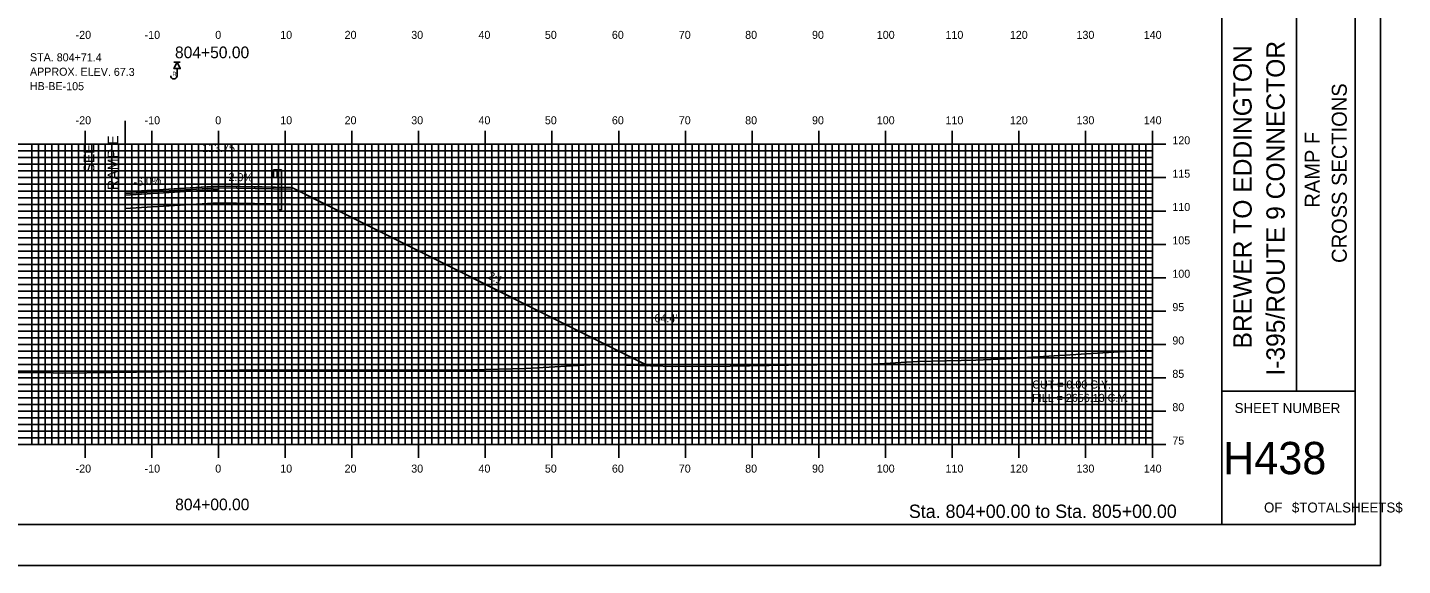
# Model space of a CAD drawing. Extents: x 485 to 829, y -1658 to -1438.
# Drawn here: x 622.5 to 828.6, y -1657.7 to -1577.1 of the extents above; entities that cross this region are included whole.
import ezdxf

# ---------------------------------------------------------------- set-up
doc = ezdxf.new("R2010")
doc.units = 0
for name, color, linetype in [('ANNOTATION', 7, 'Continuous'), ('BORDER', 7, 'Continuous'), ('BORING - REFUSAL', 7, 'Continuous'), ('D_Guardrail_Beam_Lt', 7, 'Continuous'), ('D_Roadway_Centerline', 7, 'Continuous'), ('D_Roadway_Centerline_Text', 7, 'Continuous'), ('D_Roadway_Edge_Shoulder', 7, 'Continuous'), ('D_Roadway_Edge_TW', 7, 'Continuous'), ('D_Roadway_Pavement', 7, 'Continuous'), ('D_Roadway_SlopeLines', 7, 'Continuous'), ('D_Roadway_SubGrade', 7, 'Continuous'), ('D_Text_Standard', 7, 'Continuous'), ('Default', 7, 'Continuous'), ('H_V ANNOTATION', 7, 'Continuous'), ('MAJOR', 7, 'Continuous'), ('MINOR', 7, 'Continuous'), ('PLOT BOUNDARY', 7, 'Continuous'), ('S_Roadway_Centerline', 7, 'Continuous')]:
    doc.layers.add(name, color=color, linetype=linetype)

msp = doc.modelspace()

# ---------------------------------------------------------------- linework, layer by layer
at = {"layer": 'BORDER'}
for p, q in [((801.53, -1651.6), (801.53, -1441.6)), ((812.72, -1631.6), (812.72, -1561.6)), ((801.53, -1631.6), (821.53, -1631.6))]:
    msp.add_line(p, q, dxfattribs=at)
msp.add_lwpolyline([(501.53, -1651.6), (821.53, -1651.6), (821.53, -1441.6), (501.53, -1441.6)], close=True, dxfattribs=at)
at = {"layer": 'BORING - REFUSAL'}
for p, q in [((645.41, -1582.3), (644.45, -1582.3)), ((644.93, -1583.26), (644.93, -1584.32))]:
    msp.add_line(p, q, dxfattribs=at)
msp.add_lwpolyline([(644.93, -1582.3), (645.41, -1583.26), (644.45, -1583.26)], close=True, dxfattribs=at)
msp.add_arc((644.45, -1584.32), 0.485, 180, 0, dxfattribs=at)
at = {"layer": 'D_Guardrail_Beam_Lt'}
for p, q in [((659.31, -1598.54), (659.17, -1598.64)), ((659.17, -1598.78), (659.37, -1598.92)), ((659.37, -1599.12), (659.17, -1599.25)), ((659.17, -1599.4), (659.31, -1599.5)), ((659.4, -1598.52), (659.33, -1598.53)), ((659.33, -1599.5), (659.4, -1599.52)), ((659.4, -1598.44), (660.09, -1598.44)), ((659.4, -1599.6), (659.4, -1598.44)), ((659.4, -1598.98), (659.4, -1599.05)), ((659.93, -1598.44), (659.93, -1599.6)), ((660.03, -1598.44), (660.03, -1599.6)), ((660.09, -1598.44), (660.56, -1598.44)), ((660.09, -1598.44), (660.09, -1599.6)), ((660.56, -1598.44), (660.56, -1604.44)), ((660.09, -1599.6), (659.4, -1599.6)), ((660.07, -1604.44), (660.07, -1599.6)), ((660.07, -1604.44), (660.56, -1604.44))]:
    msp.add_line(p, q, dxfattribs=at)
for centre, major_axis, start_param, end_param in [((659.22, -1598.71), (-0.0877, 0), 5.323254, 7.243116), ((659.22, -1599.33), (-0.0877, 0), 5.323254, 7.243116), ((659.34, -1598.57), (-0.0417, 0), 4.907132, 5.323254), ((659.34, -1599.46), (-0.0417, 0), 0.959931, 1.376053), ((659.32, -1598.98), (0.0789, 0), 0, 0.959931), ((659.32, -1599.05), (0.0789, 0), 5.323254, 6.283185)]:
    msp.add_ellipse(centre, major_axis=major_axis, ratio=0.995501, start_param=start_param, end_param=end_param, dxfattribs=at)
at = {"layer": 'D_Roadway_Centerline'}
msp.add_lwpolyline([(637.13, -1601.7), (648.53, -1601.02), (651.13, -1600.86), (657.67, -1600.99), (659.13, -1601.02), (659.67, -1601.03), (662.13, -1601.08), (666.39, -1603.21), (667.34, -1603.68), (675.21, -1607.61), (715.57, -1627.8)], dxfattribs=at)
at = {"layer": 'D_Roadway_Edge_Shoulder'}
for points in [[(651.13, -1600.86), (659.13, -1601.02), (659.13, -1601.02), (662.13, -1601.08), (662.13, -1601.33), (651.13, -1601.11)], [(651.13, -1600.86), (662.13, -1601.08), (662.13, -1601.33), (651.13, -1601.11)]]:
    msp.add_lwpolyline(points, close=True, dxfattribs=at)
at = {"layer": 'D_Roadway_Edge_TW'}
msp.add_lwpolyline([(637.13, -1601.7), (651.13, -1600.86), (651.13, -1601.11), (637.13, -1601.95)], close=True, dxfattribs=at)
at = {"layer": 'D_Roadway_Pavement'}
msp.add_lwpolyline([(637.13, -1601.95), (651.13, -1601.11), (651.13, -1601.36), (637.13, -1602.2)], close=True, dxfattribs=at)
msp.add_lwpolyline([(651.13, -1601.11), (651.13, -1601.36)], dxfattribs=at)
msp.add_lwpolyline([(651.13, -1601.11), (651.13, -1601.36)], dxfattribs=at)
msp.add_lwpolyline([(651.13, -1601.11), (651.13, -1601.36)], dxfattribs=at)
at = {"layer": 'D_Roadway_SlopeLines'}
msp.add_lwpolyline([(662.13, -1601.08), (715.57, -1627.8)], dxfattribs=at)
msp.add_lwpolyline([(662.13, -1601.08), (715.57, -1627.8)], dxfattribs=at)
at = {"layer": 'D_Roadway_SubGrade'}
msp.add_line((637.13, -1591.06), (637.13, -1604.2), dxfattribs=at)
for points in [[(637.13, -1602.2), (651.13, -1601.36), (651.13, -1603.36), (637.13, -1604.2)], [(651.13, -1601.36), (651.13, -1601.11), (662.13, -1601.33), (662.13, -1601.08), (667.34, -1603.68), (651.13, -1603.36)]]:
    msp.add_lwpolyline(points, close=True, dxfattribs=at)
at = {"layer": 'Default'}
msp.add_line((637.13, -1604.2), (637.13, -1593.39), dxfattribs=at)
at = {"layer": 'MAJOR'}
for p, q in [((631.13, -1592.6), (631.13, -1594.6)), ((641.13, -1592.6), (641.13, -1594.6)), ((651.13, -1592.6), (651.13, -1594.6)), ((661.13, -1592.6), (661.13, -1594.6)), ((671.13, -1592.6), (671.13, -1594.6)), ((681.13, -1592.6), (681.13, -1594.6)), ((691.13, -1592.6), (691.13, -1594.6)), ((701.13, -1592.6), (701.13, -1594.6)), ((711.13, -1592.6), (711.13, -1594.6)), ((721.13, -1592.6), (721.13, -1594.6)), ((731.13, -1592.6), (731.13, -1594.6)), ((741.13, -1592.6), (741.13, -1594.6)), ((751.13, -1592.6), (751.13, -1594.6)), ((761.13, -1592.6), (761.13, -1594.6)), ((771.13, -1592.6), (771.13, -1594.6)), ((781.13, -1592.6), (781.13, -1594.6)), ((791.13, -1592.6), (791.13, -1594.6)), ((511.13, -1594.6), (791.13, -1594.6)), ((511.13, -1594.6), (791.13, -1594.6)), ((631.13, -1639.6), (631.13, -1594.6)), ((641.13, -1639.6), (641.13, -1594.6)), ((651.13, -1639.6), (651.13, -1594.6)), ((661.13, -1639.6), (661.13, -1594.6)), ((671.13, -1639.6), (671.13, -1594.6)), ((681.13, -1639.6), (681.13, -1594.6)), ((691.13, -1639.6), (691.13, -1594.6)), ((701.13, -1639.6), (701.13, -1594.6)), ((711.13, -1639.6), (711.13, -1594.6)), ((721.13, -1639.6), (721.13, -1594.6)), ((731.13, -1639.6), (731.13, -1594.6)), ((741.13, -1639.6), (741.13, -1594.6)), ((751.13, -1639.6), (751.13, -1594.6)), ((761.13, -1639.6), (761.13, -1594.6)), ((771.13, -1639.6), (771.13, -1594.6)), ((781.13, -1639.6), (781.13, -1594.6)), ((793.14, -1594.6), (789.13, -1594.6)), ((791.13, -1639.6), (791.13, -1594.6)), ((791.13, -1639.6), (791.13, -1594.6)), ((511.13, -1599.6), (791.13, -1599.6)), ((793.14, -1599.6), (789.13, -1599.6)), ((511.13, -1604.6), (791.13, -1604.6)), ((793.14, -1604.6), (789.13, -1604.6)), ((511.13, -1609.6), (791.13, -1609.6)), ((793.14, -1609.6), (789.13, -1609.6)), ((511.13, -1614.6), (791.13, -1614.6)), ((793.14, -1614.6), (789.13, -1614.6)), ((511.13, -1619.6), (791.13, -1619.6)), ((793.14, -1619.6), (789.13, -1619.6)), ((511.13, -1624.6), (791.13, -1624.6)), ((793.14, -1624.6), (789.13, -1624.6)), ((511.13, -1629.6), (791.13, -1629.6)), ((793.14, -1629.6), (789.13, -1629.6)), ((511.13, -1634.6), (791.13, -1634.6)), ((793.14, -1634.6), (789.13, -1634.6)), ((511.13, -1639.6), (791.13, -1639.6)), ((511.13, -1639.6), (791.13, -1639.6)), ((631.13, -1641.61), (631.13, -1639.6)), ((641.13, -1641.61), (641.13, -1639.6)), ((651.13, -1641.61), (651.13, -1639.6)), ((661.13, -1641.61), (661.13, -1639.6)), ((671.13, -1641.61), (671.13, -1639.6)), ((681.13, -1641.61), (681.13, -1639.6)), ((691.13, -1641.61), (691.13, -1639.6)), ((701.13, -1641.61), (701.13, -1639.6)), ((711.13, -1641.61), (711.13, -1639.6)), ((721.13, -1641.61), (721.13, -1639.6)), ((731.13, -1641.61), (731.13, -1639.6)), ((741.13, -1641.61), (741.13, -1639.6)), ((751.13, -1641.61), (751.13, -1639.6)), ((761.13, -1641.61), (761.13, -1639.6)), ((771.13, -1641.61), (771.13, -1639.6)), ((781.13, -1641.61), (781.13, -1639.6)), ((793.14, -1639.6), (789.13, -1639.6)), ((791.13, -1641.61), (791.13, -1639.6))]:
    msp.add_line(p, q, dxfattribs=at)
at = {"layer": 'MINOR'}
for p, q in [((623.13, -1639.6), (623.13, -1594.6)), ((624.13, -1639.6), (624.13, -1594.6)), ((625.13, -1639.6), (625.13, -1594.6)), ((626.13, -1639.6), (626.13, -1594.6)), ((627.13, -1639.6), (627.13, -1594.6)), ((628.13, -1639.6), (628.13, -1594.6)), ((629.13, -1639.6), (629.13, -1594.6)), ((630.13, -1639.6), (630.13, -1594.6)), ((632.13, -1639.6), (632.13, -1594.6)), ((633.13, -1639.6), (633.13, -1594.6)), ((634.13, -1639.6), (634.13, -1594.6)), ((635.13, -1639.6), (635.13, -1594.6)), ((636.13, -1639.6), (636.13, -1594.6)), ((637.13, -1639.6), (637.13, -1594.6)), ((638.13, -1639.6), (638.13, -1594.6)), ((639.13, -1639.6), (639.13, -1594.6)), ((640.13, -1639.6), (640.13, -1594.6)), ((642.13, -1639.6), (642.13, -1594.6)), ((643.13, -1639.6), (643.13, -1594.6)), ((644.13, -1639.6), (644.13, -1594.6)), ((645.13, -1639.6), (645.13, -1594.6)), ((646.13, -1639.6), (646.13, -1594.6)), ((647.13, -1639.6), (647.13, -1594.6)), ((648.13, -1639.6), (648.13, -1594.6)), ((649.13, -1639.6), (649.13, -1594.6)), ((650.13, -1639.6), (650.13, -1594.6)), ((652.13, -1639.6), (652.13, -1594.6)), ((653.13, -1639.6), (653.13, -1594.6)), ((654.13, -1639.6), (654.13, -1594.6)), ((655.13, -1639.6), (655.13, -1594.6)), ((656.13, -1639.6), (656.13, -1594.6)), ((657.13, -1639.6), (657.13, -1594.6)), ((658.13, -1639.6), (658.13, -1594.6)), ((659.13, -1639.6), (659.13, -1594.6)), ((660.13, -1639.6), (660.13, -1594.6)), ((662.13, -1639.6), (662.13, -1594.6)), ((663.13, -1639.6), (663.13, -1594.6)), ((664.13, -1639.6), (664.13, -1594.6)), ((665.13, -1639.6), (665.13, -1594.6)), ((666.13, -1639.6), (666.13, -1594.6)), ((667.13, -1639.6), (667.13, -1594.6)), ((668.13, -1639.6), (668.13, -1594.6)), ((669.13, -1639.6), (669.13, -1594.6)), ((670.13, -1639.6), (670.13, -1594.6)), ((672.13, -1639.6), (672.13, -1594.6)), ((673.13, -1639.6), (673.13, -1594.6)), ((674.13, -1639.6), (674.13, -1594.6)), ((675.13, -1639.6), (675.13, -1594.6)), ((676.13, -1639.6), (676.13, -1594.6)), ((677.13, -1639.6), (677.13, -1594.6)), ((678.13, -1639.6), (678.13, -1594.6)), ((679.13, -1639.6), (679.13, -1594.6)), ((680.13, -1639.6), (680.13, -1594.6)), ((682.13, -1639.6), (682.13, -1594.6)), ((683.13, -1639.6), (683.13, -1594.6)), ((684.13, -1639.6), (684.13, -1594.6)), ((685.13, -1639.6), (685.13, -1594.6)), ((686.13, -1639.6), (686.13, -1594.6)), ((687.13, -1639.6), (687.13, -1594.6)), ((688.13, -1639.6), (688.13, -1594.6)), ((689.13, -1639.6), (689.13, -1594.6)), ((690.13, -1639.6), (690.13, -1594.6)), ((692.13, -1639.6), (692.13, -1594.6)), ((693.13, -1639.6), (693.13, -1594.6)), ((694.13, -1639.6), (694.13, -1594.6)), ((695.13, -1639.6), (695.13, -1594.6)), ((696.13, -1639.6), (696.13, -1594.6)), ((697.13, -1639.6), (697.13, -1594.6)), ((698.13, -1639.6), (698.13, -1594.6)), ((699.13, -1639.6), (699.13, -1594.6)), ((700.13, -1639.6), (700.13, -1594.6)), ((702.13, -1639.6), (702.13, -1594.6)), ((703.13, -1639.6), (703.13, -1594.6)), ((704.13, -1639.6), (704.13, -1594.6)), ((705.13, -1639.6), (705.13, -1594.6)), ((706.13, -1639.6), (706.13, -1594.6)), ((707.13, -1639.6), (707.13, -1594.6)), ((708.13, -1639.6), (708.13, -1594.6)), ((709.13, -1639.6), (709.13, -1594.6)), ((710.13, -1639.6), (710.13, -1594.6)), ((712.13, -1639.6), (712.13, -1594.6)), ((713.13, -1639.6), (713.13, -1594.6)), ((714.13, -1639.6), (714.13, -1594.6)), ((715.13, -1639.6), (715.13, -1594.6)), ((716.13, -1639.6), (716.13, -1594.6)), ((717.13, -1639.6), (717.13, -1594.6)), ((718.13, -1639.6), (718.13, -1594.6)), ((719.13, -1639.6), (719.13, -1594.6)), ((720.13, -1639.6), (720.13, -1594.6)), ((722.13, -1639.6), (722.13, -1594.6)), ((723.13, -1639.6), (723.13, -1594.6)), ((724.13, -1639.6), (724.13, -1594.6)), ((725.13, -1639.6), (725.13, -1594.6)), ((726.13, -1639.6), (726.13, -1594.6)), ((727.13, -1639.6), (727.13, -1594.6)), ((728.13, -1639.6), (728.13, -1594.6)), ((729.13, -1639.6), (729.13, -1594.6)), ((730.13, -1639.6), (730.13, -1594.6)), ((732.13, -1639.6), (732.13, -1594.6)), ((733.13, -1639.6), (733.13, -1594.6)), ((734.13, -1639.6), (734.13, -1594.6)), ((735.13, -1639.6), (735.13, -1594.6)), ((736.13, -1639.6), (736.13, -1594.6)), ((737.13, -1639.6), (737.13, -1594.6)), ((738.13, -1639.6), (738.13, -1594.6)), ((739.13, -1639.6), (739.13, -1594.6)), ((740.13, -1639.6), (740.13, -1594.6)), ((742.13, -1639.6), (742.13, -1594.6)), ((743.13, -1639.6), (743.13, -1594.6)), ((744.13, -1639.6), (744.13, -1594.6)), ((745.13, -1639.6), (745.13, -1594.6)), ((746.13, -1639.6), (746.13, -1594.6)), ((747.13, -1639.6), (747.13, -1594.6)), ((748.13, -1639.6), (748.13, -1594.6)), ((749.13, -1639.6), (749.13, -1594.6)), ((750.13, -1639.6), (750.13, -1594.6)), ((752.13, -1639.6), (752.13, -1594.6)), ((753.13, -1639.6), (753.13, -1594.6)), ((754.13, -1639.6), (754.13, -1594.6)), ((755.13, -1639.6), (755.13, -1594.6)), ((756.13, -1639.6), (756.13, -1594.6)), ((757.13, -1639.6), (757.13, -1594.6)), ((758.13, -1639.6), (758.13, -1594.6)), ((759.13, -1639.6), (759.13, -1594.6)), ((760.13, -1639.6), (760.13, -1594.6)), ((762.13, -1639.6), (762.13, -1594.6)), ((763.13, -1639.6), (763.13, -1594.6)), ((764.13, -1639.6), (764.13, -1594.6)), ((765.13, -1639.6), (765.13, -1594.6)), ((766.13, -1639.6), (766.13, -1594.6)), ((767.13, -1639.6), (767.13, -1594.6)), ((768.13, -1639.6), (768.13, -1594.6)), ((769.13, -1639.6), (769.13, -1594.6)), ((770.13, -1639.6), (770.13, -1594.6)), ((772.13, -1639.6), (772.13, -1594.6)), ((773.13, -1639.6), (773.13, -1594.6)), ((774.13, -1639.6), (774.13, -1594.6)), ((775.13, -1639.6), (775.13, -1594.6)), ((776.13, -1639.6), (776.13, -1594.6)), ((777.13, -1639.6), (777.13, -1594.6)), ((778.13, -1639.6), (778.13, -1594.6)), ((779.13, -1639.6), (779.13, -1594.6)), ((780.13, -1639.6), (780.13, -1594.6)), ((782.13, -1639.6), (782.13, -1594.6)), ((783.13, -1639.6), (783.13, -1594.6)), ((784.13, -1639.6), (784.13, -1594.6)), ((785.13, -1639.6), (785.13, -1594.6)), ((786.13, -1639.6), (786.13, -1594.6)), ((787.13, -1639.6), (787.13, -1594.6)), ((788.13, -1639.6), (788.13, -1594.6)), ((789.13, -1639.6), (789.13, -1594.6)), ((790.13, -1639.6), (790.13, -1594.6)), ((511.13, -1595.6), (791.13, -1595.6)), ((511.13, -1596.6), (791.13, -1596.6)), ((791.13, -1595.6), (789.13, -1595.6)), ((791.13, -1596.6), (789.13, -1596.6)), ((511.13, -1597.6), (791.13, -1597.6)), ((511.13, -1598.6), (791.13, -1598.6)), ((791.13, -1597.6), (789.13, -1597.6)), ((791.13, -1598.6), (789.13, -1598.6)), ((511.13, -1600.6), (791.13, -1600.6)), ((511.13, -1601.6), (791.13, -1601.6)), ((791.13, -1600.6), (789.13, -1600.6)), ((791.13, -1601.6), (789.13, -1601.6)), ((511.13, -1602.6), (791.13, -1602.6)), ((511.13, -1603.6), (791.13, -1603.6)), ((791.13, -1602.6), (789.13, -1602.6)), ((791.13, -1603.6), (789.13, -1603.6)), ((511.13, -1605.6), (791.13, -1605.6)), ((791.13, -1605.6), (789.13, -1605.6)), ((511.13, -1606.6), (791.13, -1606.6)), ((511.13, -1607.6), (791.13, -1607.6)), ((791.13, -1606.6), (789.13, -1606.6)), ((791.13, -1607.6), (789.13, -1607.6)), ((511.13, -1608.6), (791.13, -1608.6)), ((791.13, -1608.6), (789.13, -1608.6)), ((511.13, -1610.6), (791.13, -1610.6)), ((511.13, -1611.6), (791.13, -1611.6)), ((791.13, -1610.6), (789.13, -1610.6)), ((791.13, -1611.6), (789.13, -1611.6)), ((511.13, -1612.6), (791.13, -1612.6)), ((511.13, -1613.6), (791.13, -1613.6)), ((791.13, -1612.6), (789.13, -1612.6)), ((791.13, -1613.6), (789.13, -1613.6)), ((511.13, -1615.6), (791.13, -1615.6)), ((791.13, -1615.6), (789.13, -1615.6)), ((511.13, -1616.6), (791.13, -1616.6)), ((511.13, -1617.6), (791.13, -1617.6)), ((791.13, -1616.6), (789.13, -1616.6)), ((791.13, -1617.6), (789.13, -1617.6)), ((511.13, -1618.6), (791.13, -1618.6)), ((791.13, -1618.6), (789.13, -1618.6)), ((511.13, -1620.6), (791.13, -1620.6)), ((511.13, -1621.6), (791.13, -1621.6)), ((791.13, -1620.6), (789.13, -1620.6)), ((791.13, -1621.6), (789.13, -1621.6)), ((511.13, -1622.6), (791.13, -1622.6)), ((511.13, -1623.6), (791.13, -1623.6)), ((791.13, -1622.6), (789.13, -1622.6)), ((791.13, -1623.6), (789.13, -1623.6)), ((511.13, -1625.6), (791.13, -1625.6)), ((791.13, -1625.6), (789.13, -1625.6)), ((511.13, -1626.6), (791.13, -1626.6)), ((511.13, -1627.6), (791.13, -1627.6)), ((791.13, -1626.6), (789.13, -1626.6)), ((791.13, -1627.6), (789.13, -1627.6)), ((511.13, -1628.6), (791.13, -1628.6)), ((791.13, -1628.6), (789.13, -1628.6)), ((511.13, -1630.6), (791.13, -1630.6)), ((511.13, -1631.6), (791.13, -1631.6)), ((791.13, -1630.6), (789.13, -1630.6)), ((791.13, -1631.6), (789.13, -1631.6)), ((511.13, -1632.6), (791.13, -1632.6)), ((511.13, -1633.6), (791.13, -1633.6)), ((791.13, -1632.6), (789.13, -1632.6)), ((791.13, -1633.6), (789.13, -1633.6)), ((511.13, -1635.6), (791.13, -1635.6)), ((511.13, -1636.6), (791.13, -1636.6)), ((791.13, -1635.6), (789.13, -1635.6)), ((791.13, -1636.6), (789.13, -1636.6)), ((511.13, -1637.6), (791.13, -1637.6)), ((511.13, -1638.6), (791.13, -1638.6)), ((791.13, -1637.6), (789.13, -1637.6)), ((791.13, -1638.6), (789.13, -1638.6))]:
    msp.add_line(p, q, dxfattribs=at)
at = {"layer": 'PLOT BOUNDARY'}
msp.add_lwpolyline([(485.35, -1657.72), (825.35, -1657.72), (825.35, -1437.72), (485.35, -1437.72)], close=True, dxfattribs=at)
at = {"layer": 'S_Roadway_Centerline'}
msp.add_lwpolyline([(614.3, -1628.78), (626.36, -1628.86), (627.7, -1628.88), (646.29, -1628.65), (654.09, -1628.47), (661.49, -1628.46), (667.25, -1628.38), (680.54, -1628.45), (684.05, -1628.43), (687.11, -1628.43), (697.22, -1628.18), (707.64, -1627.58), (708.4, -1627.58), (719.63, -1627.92), (727.84, -1627.84), (736.56, -1627.71), (749.35, -1627.53), (755.9, -1627.14), (764.69, -1626.95), (769.15, -1626.73), (782.07, -1625.95), (788.7, -1625.57), (789.58, -1625.52), (790.99, -1625.57), (791.13, -1625.58)], dxfattribs=at)

# ---------------------------------------------------------------- texts
at = {"layer": 'ANNOTATION'}
for s, height, rotation, p in [('RAMP E', 1.6, 90, (636.12, -1601.47)), ('SEE', 1.6, 90, (632.52, -1598.86)), ('-6.0%', 1.2, 3.4336, (638.42, -1600.85)), ('-2.0%', 1.2, 358.8535, (652.09, -1600.08)), ('2:1', 1.2, 333.4349, (691.39, -1614.67))]:
    msp.add_text(s, height=height, rotation=rotation, dxfattribs=at).set_placement(p)
at = {"layer": 'BORDER'}
for s, height, p in [('BREWER TO EDDINGTON', 2.7557, (806.02, -1625.2)), ('I-395/ROUTE 9 CONNECTOR', 2.7557, (810.98, -1629.27)), ('CROSS SECTIONS', 2.25, (820.28, -1612.38)), ('RAMP F', 2.25, (816.23, -1604.1))]:
    msp.add_text(s, height=height, rotation=90, dxfattribs=at).set_placement(p)
for s, height, p in [('SHEET NUMBER', 1.4905, (803.47, -1634.87)), ('H438', 4.839, (801.74, -1644.04)), ('OF', 1.491, (807.87, -1649.78)), ('$TOTALSHEETS$', 1.4905, (812.05, -1649.78))]:
    msp.add_text(s, height=height, dxfattribs=at).set_placement(p)
at = {"layer": 'BORING - REFUSAL'}
for s, p in [('STA. 804+71.4', (622.87, -1582.15)), ('APPROX. ELEV. 67.3', (622.87, -1584.31)), ('HB-BE-105', (622.86, -1586.47))]:
    msp.add_text(s, height=1.2, rotation=359.8142, dxfattribs=at).set_placement(p)
msp.add_text('R', height=0.64, dxfattribs=at).set_placement((644.23, -1584.38))
at = {"layer": 'D_Roadway_Centerline_Text'}
msp.add_text('113.75', height=1.2, dxfattribs=at).set_placement((648.7, -1595.76))
at = {"layer": 'D_Text_Standard'}
for s, p in [("64.4'", (716.5, -1621.27)), ('CUT = 0.00 C.Y.', (773.13, -1631.2)), ('FILL = 2656.13 C.Y.', (773.13, -1633.2))]:
    msp.add_text(s, height=1.2, dxfattribs=at).set_placement(p)
at = {"layer": 'H_V ANNOTATION'}
for s, height, p in [('-20', 1.2, (629.72, -1578.8)), ('-10', 1.2, (640.06, -1578.8)), ('0', 1.2, (650.65, -1578.8)), ('10', 1.2, (660.39, -1578.8)), ('20', 1.2, (670.04, -1578.8)), ('30', 1.2, (680.03, -1578.8)), ('40', 1.2, (690.11, -1578.8)), ('50', 1.2, (700.06, -1578.8)), ('60', 1.2, (710.11, -1578.8)), ('70', 1.2, (720.14, -1578.8)), ('80', 1.2, (730.09, -1578.8)), ('90', 1.2, (740.11, -1578.8)), ('100', 1.2, (749.82, -1578.8)), ('110', 1.2, (760.12, -1578.8)), ('120', 1.2, (769.77, -1578.8)), ('130', 1.2, (779.76, -1578.8)), ('140', 1.2, (789.84, -1578.8)), ('804+50.00', 1.75, (644.61, -1581.7)), ('-20', 1.2, (629.72, -1591.6)), ('-10', 1.2, (640.06, -1591.6)), ('0', 1.2, (650.65, -1591.6)), ('10', 1.2, (660.39, -1591.6)), ('20', 1.2, (670.04, -1591.6)), ('30', 1.2, (680.03, -1591.6)), ('40', 1.2, (690.11, -1591.6)), ('50', 1.2, (700.06, -1591.6)), ('60', 1.2, (710.11, -1591.6)), ('70', 1.2, (720.14, -1591.6)), ('80', 1.2, (730.09, -1591.6)), ('90', 1.2, (740.11, -1591.6)), ('100', 1.2, (749.82, -1591.6)), ('110', 1.2, (760.12, -1591.6)), ('120', 1.2, (769.77, -1591.6)), ('130', 1.2, (779.76, -1591.6)), ('140', 1.2, (789.84, -1591.6)), ('120', 1.2, (794.13, -1594.6)), ('115', 1.2, (794.13, -1599.6)), ('110', 1.2, (794.13, -1604.6)), ('105', 1.2, (794.13, -1609.6)), ('100', 1.2, (794.13, -1614.6)), ('95', 1.2, (794.13, -1619.6)), ('90', 1.2, (794.13, -1624.6)), ('85', 1.2, (794.13, -1629.6)), ('80', 1.2, (794.13, -1634.6)), ('75', 1.2, (794.13, -1639.6)), ('-20', 1.2, (629.72, -1643.8)), ('-10', 1.2, (640.06, -1643.8)), ('0', 1.2, (650.65, -1643.8)), ('10', 1.2, (660.39, -1643.8)), ('20', 1.2, (670.04, -1643.8)), ('30', 1.2, (680.03, -1643.8)), ('40', 1.2, (690.11, -1643.8)), ('50', 1.2, (700.06, -1643.8)), ('60', 1.2, (710.11, -1643.8)), ('70', 1.2, (720.14, -1643.8)), ('80', 1.2, (730.09, -1643.8)), ('90', 1.2, (740.11, -1643.8)), ('100', 1.2, (749.82, -1643.8)), ('110', 1.2, (760.12, -1643.8)), ('120', 1.2, (769.77, -1643.8)), ('130', 1.2, (779.76, -1643.8)), ('140', 1.2, (789.84, -1643.8)), ('804+00.00', 1.75, (644.64, -1649.45)), ('Sta. 804+00.00 to Sta. 805+00.00', 2.0004, (754.63, -1650.6))]:
    msp.add_text(s, height=height, dxfattribs=at).set_placement(p)

doc.saveas('drawing.dxf')
